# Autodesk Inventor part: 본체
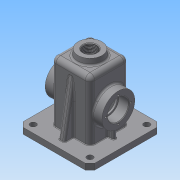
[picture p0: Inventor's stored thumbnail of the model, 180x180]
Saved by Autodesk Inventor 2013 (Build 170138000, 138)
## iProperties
Created: 2018-10
Part Number: 본체
Material: 일반
Document SubType Name: Modeling
Designer: Administrator
Density: 1 g/cm^3
Author: Administrator
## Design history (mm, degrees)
sketch "스케치1"
  geometry: L1 (-32.5, 32.5)-(32.5, 32.5); L2 (32.5, 32.5)-(32.5, -32.5); L3 (32.5, -32.5)-(-32.5, -32.5); L4 (-32.5, -32.5)-(-32.5, 32.5); L5 (-32.5, 32.5)-(32.5, -32.5); L6 (32.5, 32.5)-(-32.5, -32.5); 1 further point
  constraints: 12 end point, 2 midpoint, 2 parallel, 1 horizontal, 1 perpendicular
  dimensions: "d0" = 65 distance of L2.end L3.end; "d1" = 65 distance of L1.end L2.end
extrude "돌출1" new body sketch "스케치1" stored distance "d2" = 110; taper "d3" = 0 deg
sketch "스케치2"
  geometry: L1 (-110, 0)-(-110, 65) reference; C1 r 27.5 at (-55, 32.5); 2 further points
  constraints: 1 centre point, 1 horizontal alignment, 1 midpoint
  dimensions: "d4" = 55 diameter of C1; "d5" = 55 distance of point (-110, 32.5) C1.centre
feature "쉘1" dims "d6" = 5
fillet "모깎기1" dims "d7" = 8
fillet "모깎기2" dims "d8" = 8
extrude "돌출2" join sketch "스케치2" distance "d9" = 15; taper "d10" = 0 deg
sketch "스케치3"
  geometry: C1 r 27.5 at (0, 0) reference; C2 r 17.5 at (0, 0)
  constraints: 1 centre point, 1 coincident
  dimensions: "d11" = 35 diameter of C2
extrude "돌출3" cut sketch "스케치3" distance "d13" = 17; taper "d14" = 0 deg
sketch "스케치5"
  geometry: C1 r 27.5 at (-55, 24.5); 1 further point
  constraints: 1 centre point, 1 coincident
  dimensions: "d16" = 55 diameter of C1
extrude "돌출4" join sketch "스케치5" distance "d17" = 15; taper "d18" = 0 deg
sketch "스케치6"
  geometry: C1 r 27.5 at (0, 0) reference; C2 r 17.5 at (0, 0)
  constraints: 1 centre point, 1 coincident
  dimensions: "d20" = 35 diameter of C2
extrude "돌출5" cut sketch "스케치6" distance "d21" = 17; taper "d22" = 0 deg
sketch "스케치7"
  geometry: C1 r 17.5 at (0, 0) reference; C2 r 15 at (0, 0)
  constraints: 1 centre point, 1 coincident
  dimensions: "d23" = 30 diameter of C2
extrude "돌출6" cut sketch "스케치7" stored distance "d24" = 17; taper "d25" = 0 deg
sketch "스케치8"
  geometry: L1 (-32.5, 24.5)-(-32.5, -24.5) reference; L2 (-24.5, -32.5)-(24.5, -32.5) reference; L3 (32.5, -24.5)-(32.5, 24.5) reference; L4 (24.5, 32.5)-(-24.5, 32.5) reference; L5 (-60, 60)-(60, 60); L6 (60, 60)-(60, -60); L7 (60, -60)-(-60, -60); L8 (-60, -60)-(-60, 60); L9 (-60, 60)-(60, -60); L10 (60, 60)-(-60, -60); A1 r 8 centre (-24.5, 24.5) between (-24.5, 32.5) and (-32.5, 24.5) reference; A2 r 8 centre (-24.5, -24.5) between (-32.5, -24.5) and (-24.5, -32.5) reference; A3 r 8 centre (24.5, -24.5) between (24.5, -32.5) and (32.5, -24.5) reference; A4 r 8 centre (24.5, 24.5) between (32.5, 24.5) and (24.5, 32.5) reference; 1 further point
  constraints: 12 end point, 2 midpoint, 2 parallel, 1 horizontal, 1 perpendicular
  dimensions: "d26" = 120 distance of L5.start L5.end; "d28" = 120 distance of L5.end L6.end
extrude "돌출7" join sketch "스케치8" distance "d29" = 10; taper "d30" = 0 deg
chamfer "모따기1" distance "d31" = 8; stored, may be unused: second distance "d32" = 2, angle "d33" = 45 deg
node "작업 평면1"
sketch "스케치9"
  geometry: C1 r 20 at (0, 0); 1 further point
  constraints: 1 centre point, 1 coincident
  dimensions: "d35" = 40 diameter of C1
extrude "돌출8" join sketch "스케치9" stored distance "d36" = 10; taper "d37" = 7 deg
hole "구멍1" diameter "d40" = 22.835; stored, may be unused: countersink angle "d44" = 90 deg, drill point angle "d46" = 0 deg; dims "d41" = 20, "d42" = 4, "d43" = 2, "d45" = 20, "d116" = 10, "d117" = 10
sketch "스케치10"
  geometry: L1 (48, -45)-(40.815, -4.251); L2 (60, -45)-(60, -55) reference; L3 (52, -45)-(60, -45) reference; 1 further point
  constraints: 2 end point, 1 point on line
  dimensions: "d50" = 12 distance from line of L2 L1.start; "d52" = 10 deg angle of L2 L1
feature "리브1" sketch "스케치10" dims "d53" = 1, "d54" = 10, "d55" = 0, "d56" = 0, "d57" = 1, "d58" = 1
sketch "스케치11"
  geometry: L1 (-42.5, -29.454)-(-42.5, -45); L2 (52, -45)-(-52, -45) reference; L3 (-32.5, -45)-(-32.5, -12.49) reference; L4 (-27.5, 50)-(-27.5, -55) reference; 2 further points
  constraints: 2 end point, 1 point on line, 1 vertical
  dimensions: "d60" = 15 distance between parallel lines of L4 L1
fillet "모깎기5" dims "d61" = 3
fillet "모깎기6" dims "d62" = 3
feature "리브2" dims "d63" = 1, "d64" = 6, "d65" = 0, "d66" = 0, "d67" = 1, "d68" = 1
fillet "모깎기8" dims "d70" = 3
fillet "모깎기9" dims "d71" = 3
chamfer "모따기2" distance "d73" = 1; stored, may be unused: second distance "d74" = 2, angle "d75" = 45 deg
sketch "스케치12"
  geometry: L1 (0, 0)-(-21, 0); C1 r 18.5 at (0, 0) reference; 1 further point
  constraints: 2 end point, 1 coincident, 1 horizontal
  dimensions: "d77" = 21 distance of L1.start L1.end
hole "구멍2" sketch "스케치12" at (-21, 0) diameter "d78" = 3.242; stored, may be unused: countersink angle "d82" = 90 deg, drill point angle "d84" = 118 deg; dims "d79" = 8, "d80" = 4, "d81" = 2, "d83" = 10
fillet "모깎기11" dims "d88" = 3
chamfer "모따기3" distance "d89" = 1; stored, may be unused: second distance "d90" = 2, angle "d91" = 45 deg
fillet "모깎기15" dims "d95" = 3
fillet "모깎기17" dims "d97" = 3
sketch "스케치13"
  geometry: C1 r 5 at (-47.5, 47.5); C2 r 5 at (-47.5, -47.5); C3 r 5 at (47.5, 47.5); C4 r 5 at (47.5, -47.5); 1 further point
  constraints: 4 centre point, 2 horizontal alignment, 2 vertical alignment
  dimensions: "d99" = 10 diameter of C1; "d100" = 10 diameter of C2; "d101" = 10 diameter of C3; "d102" = 10 diameter of C4; "d103" = 95 distance of C4.centre C3.centre; "d104" = 95 distance of C3.centre C1.centre; "d105" = 47.5 horizontal distance of point (0, 0) C3.centre; "d106" = 47.5 horizontal distance of point (0, 0) C1.centre
extrude "돌출9" cut sketch "스케치13" distance "d107" = 10; taper "d108" = 0 deg
sketch "스케치14"
  geometry: L1 (0, 57)-(-92, 57) reference; L2 (18, 44.5)-(18, 4.5) reference; 1 further point
  constraints: 1 other
  dimensions: "d109" = 32.5 distance from line of point (-8, 24.5) L1; "d110" = 26 distance from line of L2 point (-8, 24.5)
feature "엠보싱1" sketch "스케치14" dims "d111" = 0.5, "d112" = 0
fillet "모깎기19" dims "d113" = 1
fillet "모깎기20" dims "d114" = 3
fillet "모깎기21" dims "d115" = 3
fillet "모깎기22" dims "d118" = 0.3
node "솔리드1"
mirror "대칭1"
mirror "대칭2"
pattern_circular "원형 패턴1" dims angle "d86" = 360 deg
mirror "대칭3"
other parameters: "d34" = 65
